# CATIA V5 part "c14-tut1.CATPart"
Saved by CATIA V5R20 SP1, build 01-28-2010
Part number: Part1
Bounding box of the stored display mesh (mm): x 0 to 46, y -104 to 104, z 0 to 68
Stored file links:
  D:\v5_r20\psrt_files_downloaded\c14\c14-catia-v5r20-tut01\c14-tut1.CATPart
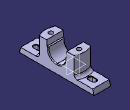
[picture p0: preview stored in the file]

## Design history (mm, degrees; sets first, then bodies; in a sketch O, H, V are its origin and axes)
Body1 (main body)
  Sketch1 on yz-plane, origin (0, 0, 0), H (0, 1, 0), V (0, 0, 1)
    axis line L1 (0, -39.4814) -> (0, 63.0107)
    point P1 (0, -39.4814)
    line L2 (0, 0) -> (104, 0)
    point P3 (104, 0)
    line L3 (104, 0) -> (100, 14)
    point P4 (100, 14)
    line L4 (100, 14) -> (54, 14)
    point P5 (54, 14)
    line L5 (54, 14) -> (54, 68)
    point P6 (54, 68)
    line L6 (54, 68) -> (28, 68)
    point P7 (28, 68)
    line L7 (28, 68) -> (28, 52)
    point P8 (28, 52)
    line L8 (28, 52) -> (23.6643, 52)
    point P9 (23.6643, 52)
    arc A1 centre (0, 48) radius 24 from (23.6643, 52) to (0, 24) cw
    point P10 (0, 48)
    point P11 (0, 24)
    point P12 (-104, 0)
    point P13 (0, 0)
    line L9 (0, 0) -> (-104, 0)
    point P14 (0, 24)
    point P15 (-23.6643, 52)
    point P16 (0, 48)
    arc A2 centre (0, 48) radius 24 from (-23.6643, 52) to (0, 24) ccw
    point P17 (-54, 68)
    point P18 (-28, 68)
    point P19 (-28, 52)
    line L10 (-54, 68) -> (-28, 68)
    line L11 (-28, 68) -> (-28, 52)
    line L12 (-28, 52) -> (-23.6643, 52)
    point P20 (-54, 14)
    line L13 (-54, 14) -> (-54, 68)
    point P21 (-100, 14)
    line L14 (-100, 14) -> (-54, 14)
    line L15 (-104, 0) -> (-100, 14)
    distance P3 P12 = 208
    length L3 V = 14
    distance P3 P6 V = 68
    distance L5 L13 = 108
    distance P18 P7 = 56
    distance P19 P18 = 16
    distance P15 P16 V = 4
    length L15 H = 4
    radius A1 = 24
    coincidence: P1 V, P10 L1, L1 P11, O P13, P11 P14
    vertical: L1 V, L5 V, L7 V
    horizontal: L2 H, L4 H, L6 H, L8 H
    symmetry: P3 P12 L1, O P13 L1, L2 L9 L1, P11 P14 L1, P9 P15 L1, A1 A2 L1, P6 P17 L1, P7 P18 L1, P8 P19 L1, L6 L10 L1, L7 L11 L1, L8 L12 L1, P5 P20 L1, L5 L13 L1, P4 P21 L1, L4 L14 L1, L3 L15 L1
  Pad1: profile Sketch1, direction (1, 0, 0), length 46
  Sketch2 on face of Pad1, origin (0, 0, 14), H (1, 0, 0), V (0, 1, 0)
    arc A1 centre (23, 4) radius 50 from (0, 48.3959) to (46, 48.3959) cw
    point P2 (0, 48.3959)
    point P3 (46, 48.3959)
    reference projected line E1 (46, 54) -> (46, 28) from edge [face of Pad1 | face of Pad1]
    construction line L1 (46, 48.3959) -> (0, 48.3959)
    reference projected line E2 (0, 54) -> (46, 54) from edge [face of Pad1 | face of Pad1]
    axis line L2 (-10.6771, 0) -> (51.171, 0)
    point P4 (-10.6771, 0)
    point P6 (46, -48.3959)
    point P7 (0, -48.3959)
    arc A2 centre (23, -4) radius 50 from (0, -48.3959) to (46, -48.3959) ccw
    line L3 (0, -48.3959) -> (0, 48.3959)
    line L4 (46, 48.3959) -> (46, -48.3959)
    radius A1 = 50
    coincidence: P2 V, P3 E1, P4 H
    horizontal: L1 H, L2 H
    tangency: A1 E2
    symmetry: P3 P6 L2, P2 P7 L2, A1 A2 L2
    vertical: L3 V, L4 V
  Pocket1: profile Sketch2, direction (0, 0, 1), through (limit type 3), outer side
  Sketch3 on face of Pad1, origin (0, 0, 0), H (1, 0, 0), V (0, -1, 0)
    axis line L1 (46, -104) -> (0, 104)
    point P1 (46, -104)
    point P2 (0, 104)
    reference projected point E1 (46, -104) from vertex [face of Pad1 | face of Pad1 | face of Pad1]
    reference projected point E2 (0, 104) from vertex [face of Pad1 | face of Pad1 | face of Pad1]
    point P3 (23, 0)
    line L2 (40.5, 97.5) -> (40.5, -97.5)
    line L3 (40.5, -97.5) -> (5.5, -97.5)
    line L4 (5.5, -97.5) -> (5.5, 97.5)
    line L5 (5.5, 97.5) -> (40.5, 97.5)
    length L3 = 35
    length L2 = 195
    coincidence: P1 E1, P2 E2
    midpoint: P3 L1
    vertical: L2 V, L4 V
    horizontal: L3 H, L5 H
    equidistance: L2 L4 P3, L3 L5 P3
  Pocket2: profile Sketch3, direction (0, 0, 1), length 2
  Sketch4 on face of Pad1, origin (0, 0, 0), H (1, 0, 0), V (0, -1, 0)
    point P1 (23, 39)
    line L1 (36, 52) -> (36, 26)
    line L2 (36, 26) -> (10, 26)
    line L3 (10, 26) -> (10, 52)
    line L4 (10, 52) -> (36, 52)
    construction line L5 (40.5, 0) -> (5.5, 0)
    point P6 (40.5, 0)
    point P7 (5.5, 0)
    reference projected line E1 (40.5, -97.5) -> (40.5, 0) from edge [face of Pad1 | face of Pocket2]
    reference projected line E2 (5.5, 0) -> (5.5, -97.5) from edge [face of Pad1 | face of Pocket2]
    axis line L6 (23, 39) -> (23, 0)
    point P8 (23, 0)
    reference intersected line E3 (0, 104) -> (46, 104) from face of Pad1
    length L3 = 26
    length L4 = 26
    distance L2 E3 = 78
    vertical: L1 V, L3 V, L6 V
    horizontal: L2 H, L4 H, L5 H
    equidistance: L1 L3 P1, L2 L4 P1
    coincidence: P6 H, E1 P6, P7 E2, P8 L5
    midpoint: P8 L5
  Pocket3: profile Sketch4, direction (0, 0, 1), length 10
  Sketch5 on face of Pad1, origin (24.629, 46.0353, 68), H (1, 0, 0), V (0, 1, 0)
    point P1 (-1.629, -85.0353)
    axis line L1 (11.371, -98.0353) -> (-14.629, -72.0353)
    point P2 (11.371, -98.0353)
    point P3 (-14.629, -72.0353)
    reference projected point E1 (11.371, -98.0353) from vertex [face of Pocket3 | face of Pocket3 | face of Pocket3]
    reference projected point E2 (-14.629, -72.0353) from vertex [face of Pocket3 | face of Pocket3 | face of Pocket3]
    coincidence: P2 E1, P3 E2
    midpoint: P1 L1
  Hole1: placed by Sketch5, at (23, -39, 68) direction (0, 0, -1), diameter 12, through (limit type 3)
  Sketch6 on face of Pad1, origin (0, 0, 14), H (1, 0, 0), V (0, 1, 0)
    construction line L1 (23, -71) -> (23, -81)
    point P2 (23, -81)
    line L2 (29, -71) -> (29, -81)
    line L3 (17, -81) -> (17, -71)
    arc A1 centre (23, -81) radius 6 from (29, -81) to (17, -81) cw
    arc A2 centre (23, -71) radius 6 from (17, -71) to (29, -71) cw
    reference projected line E1 (46, -54) -> (46, -100) from edge of Pad1
    reference projected line E2 (0, -104) -> (46, -104) from edge [face of Pad1 | face of Pad1]
    distance L1 E1 = 23
    distance P2 E2 = 23
    radius A1 = 6
    length L1 = 10
    vertical: L1 V
    tangency: A1 L2, A2 L2, A1 L3, A2 L3
    parallelism: L1 L2
  Pocket4: profile Sketch6, direction (0, 0, -1), through (limit type 3)
  Mirror1: of Pocket3, Sketch4, Hole1, Pocket4, Sketch6, about zx-plane
  Fillet1: radius 8, on 2 edges
  Chamfer1: length 1, angle 45, on 2 edges
  Chamfer2: length 2, angle 45, on edge [face of Pad1 | face of Pad1] (x2)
